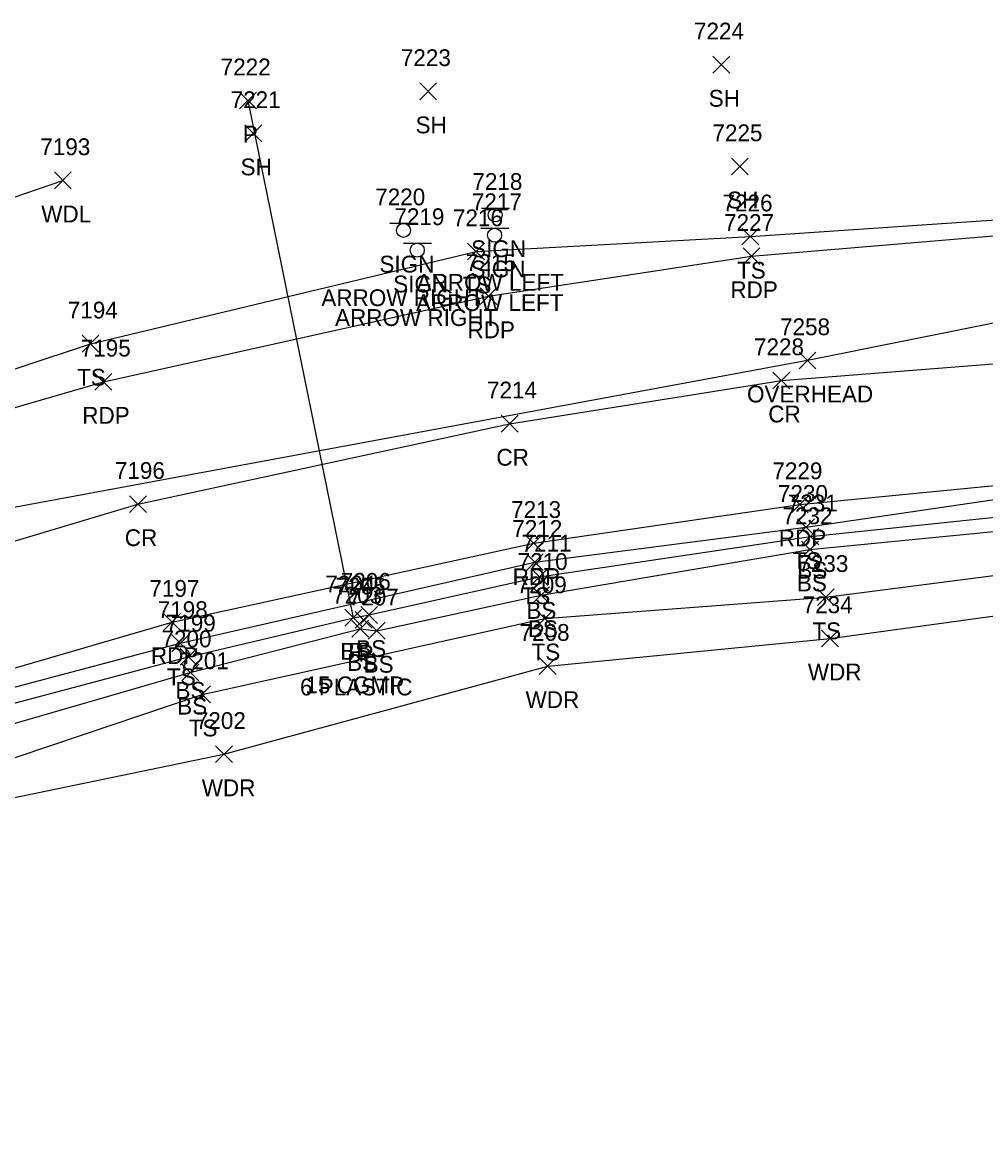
# Model space of a CAD drawing. Extents: x 1611797 to 1633212, y 298978 to 305475.
# Drawn here: x 1624498.3 to 1624612.9, y 304428 to 304561.2 of the extents above; entities that cross this region are included whole.
import ezdxf

# ---------------------------------------------------------------- set-up
doc = ezdxf.new("R2010")
doc.units = 0
for name, color, linetype in [('D_A', 7, 'Continuous'), ('D_C', 7, 'Continuous'), ('D_I', 7, 'Continuous'), ('D_TIC', 7, 'Continuous'), ('DCP', 7, 'Continuous'), ('L_A', 7, 'Continuous'), ('L_C', 7, 'Continuous'), ('L_I', 7, 'Continuous'), ('L_TIC', 7, 'Continuous'), ('LAWA', 7, 'Continuous'), ('LELB', 7, 'Continuous'), ('P_A', 7, 'Continuous'), ('P_I', 7, 'Continuous'), ('P_TIC', 7, 'Continuous'), ('PET', 7, 'Continuous'), ('PRC', 7, 'Continuous'), ('S_A', 7, 'Continuous'), ('S_C', 7, 'Continuous'), ('S_I', 7, 'Continuous'), ('SSGN', 7, 'Continuous'), ('U_A', 7, 'Continuous'), ('U_I', 7, 'Continuous'), ('U_TIC', 7, 'Continuous'), ('UCO', 7, 'Continuous')]:
    doc.layers.add(name, color=color, linetype=linetype)

msp = doc.modelspace()

# ---------------------------------------------------------------- linework, layer by layer
at = {"layer": 'D_TIC'}
for points in [[(1624524.14, 304550.87), (1624526.14, 304552.87)], [(1624526.14, 304550.87), (1624524.14, 304552.87)], [(1624536.67, 304489.32), (1624538.67, 304491.32)], [(1624538.67, 304489.32), (1624536.67, 304491.32)], [(1624537.9, 304489.07), (1624539.9, 304491.07)], [(1624539.9, 304489.07), (1624537.9, 304491.07)]]:
    msp.add_lwpolyline(points, dxfattribs=at)
at = {"layer": 'DCP'}
msp.add_lwpolyline([(1624537.67, 304490.32), (1624525.14, 304551.87)], dxfattribs=at)
at = {"layer": 'L_TIC'}
for points in [[(1624580.46, 304555.14), (1624582.46, 304557.14)], [(1624582.46, 304555.14), (1624580.46, 304557.14)], [(1624545.58, 304551.97), (1624547.58, 304553.97)], [(1624547.58, 304551.97), (1624545.58, 304553.97)], [(1624524.77, 304546.97), (1624526.77, 304548.97)], [(1624526.77, 304546.97), (1624524.77, 304548.97)], [(1624582.66, 304543.03), (1624584.66, 304545.03)], [(1624584.66, 304543.03), (1624582.66, 304545.03)], [(1624502.11, 304541.37), (1624504.11, 304543.37)], [(1624504.11, 304541.37), (1624502.11, 304543.37)], [(1624583.91, 304534.68), (1624585.91, 304536.68)], [(1624585.91, 304534.68), (1624583.91, 304536.68)], [(1624551.27, 304532.91), (1624553.27, 304534.91)], [(1624553.27, 304532.91), (1624551.27, 304534.91)], [(1624505.38, 304521.93), (1624507.38, 304523.93)], [(1624507.38, 304521.93), (1624505.38, 304523.93)], [(1624590.53, 304500.1), (1624592.53, 304502.1)], [(1624592.53, 304500.1), (1624590.53, 304502.1)], [(1624591.05, 304498.97), (1624593.05, 304500.97)], [(1624593.05, 304498.97), (1624591.05, 304500.97)], [(1624591, 304497.44), (1624593, 304499.44)], [(1624593, 304497.44), (1624591, 304499.44)], [(1624558.27, 304495.93), (1624560.27, 304497.93)], [(1624560.27, 304495.93), (1624558.27, 304497.93)], [(1624558.82, 304494.18), (1624560.82, 304496.18)], [(1624560.82, 304494.18), (1624558.82, 304496.18)], [(1624559, 304492), (1624561, 304494)], [(1624561, 304492), (1624559, 304494)], [(1624592.88, 304491.76), (1624594.88, 304493.76)], [(1624594.88, 304491.76), (1624592.88, 304493.76)], [(1624536.67, 304489.32), (1624538.67, 304491.32)], [(1624538.67, 304489.32), (1624536.67, 304491.32)], [(1624538.56, 304489.64), (1624540.56, 304491.64)], [(1624540.56, 304489.64), (1624538.56, 304491.64)], [(1624559.46, 304489.23), (1624561.46, 304491.23)], [(1624561.46, 304489.23), (1624559.46, 304491.23)], [(1624537.49, 304487.99), (1624539.49, 304489.99)], [(1624539.49, 304487.99), (1624537.49, 304489.99)], [(1624539.45, 304487.77), (1624541.45, 304489.77)], [(1624541.45, 304487.77), (1624539.45, 304489.77)], [(1624516.08, 304486.27), (1624518.08, 304488.27)], [(1624518.08, 304486.27), (1624516.08, 304488.27)], [(1624593.39, 304486.85), (1624595.39, 304488.85)], [(1624595.39, 304486.85), (1624593.39, 304488.85)], [(1624517.06, 304484.67), (1624519.06, 304486.67)], [(1624519.06, 304484.67), (1624517.06, 304486.67)], [(1624517.27, 304482.79), (1624519.27, 304484.79)], [(1624519.27, 304482.79), (1624517.27, 304484.79)], [(1624559.79, 304483.56), (1624561.79, 304485.56)], [(1624561.79, 304483.56), (1624559.79, 304485.56)], [(1624518.68, 304480.19), (1624520.68, 304482.19)], [(1624520.68, 304480.19), (1624518.68, 304482.19)], [(1624521.27, 304473.07), (1624523.27, 304475.07)], [(1624523.27, 304473.07), (1624521.27, 304475.07)]]:
    msp.add_lwpolyline(points, dxfattribs=at)
at = {"layer": 'LAWA'}
for points in [[(1624088.25, 304303.5), (1624106.81, 304320.98), (1624153.79, 304356.6), (1624200.5, 304392.1), (1624247.6, 304427), (1624285.25, 304446.91), (1624325.08, 304470.25), (1624369.06, 304488.79), (1624425.3, 304516.01), (1624470.84, 304531.32), (1624503.11, 304542.37)], [(1624186.93, 304294.55), (1624240.75, 304330.36), (1624281.9, 304359.85), (1624320.17, 304387.37), (1624354.03, 304407.62), (1624397.63, 304429.96), (1624419.55, 304440), (1624447.61, 304454.04), (1624487.94, 304466.98), (1624522.27, 304474.07), (1624560.79, 304484.56), (1624594.39, 304487.85), (1624625.21, 304492.09), (1624656.2, 304492.85), (1624695.81, 304490.79), (1624736.39, 304487.29), (1624770.57, 304478.97), (1624808.86, 304473.48), (1624838.37, 304462.56)]]:
    msp.add_lwpolyline(points, dxfattribs=at)
at = {"layer": 'LELB'}
for points in [[(1624095.54, 304298.86), (1624107.13, 304308.7), (1624163.15, 304341.2), (1624211.36, 304376.85), (1624256.11, 304405.01), (1624295.12, 304429.63), (1624332.27, 304455.09), (1624374.78, 304478.34), (1624401.92, 304484.81), (1624434.05, 304498.5), (1624472.98, 304511.84), (1624506.38, 304522.93), (1624552.27, 304533.91), (1624584.91, 304535.68), (1624625.23, 304538.42), (1624653.95, 304544.88), (1624697.41, 304542.2), (1624744.04, 304535.67), (1624782.56, 304529.52), (1624820.4, 304520.29), (1624849.23, 304510.65), (1624882.95, 304501.96), (1624884.04, 304505.26)], [(1624181.13, 304309.78), (1624231.77, 304345.18), (1624273.89, 304372.63), (1624313.92, 304397.95), (1624349.41, 304418.31), (1624391.23, 304441.37), (1624414.63, 304450.88), (1624422.5, 304457.15), (1624425.95, 304456.68), (1624445.07, 304463.44), (1624483.55, 304478.38), (1624517.08, 304487.27), (1624559.27, 304496.93), (1624591.53, 304501.1), (1624624.74, 304505.99)], [(1624181.83, 304308.22), (1624233.12, 304343.37), (1624274.63, 304371.3), (1624314.75, 304397.03), (1624350.32, 304417.49), (1624392.11, 304440.37), (1624415, 304449.13), (1624422.64, 304454.19), (1624424.46, 304454.85), (1624445.65, 304462.42), (1624484.46, 304476.74), (1624518.06, 304485.67), (1624537.67, 304490.32), (1624539.56, 304490.64), (1624559.82, 304495.18), (1624592.05, 304499.97), (1624624.64, 304503.4)], [(1624183.73, 304304.83), (1624234.53, 304340.54), (1624276.44, 304368.9), (1624316.24, 304394.62), (1624351.26, 304415.55), (1624393.38, 304438.07), (1624416.16, 304446.51), (1624422.67, 304451.72), (1624426.18, 304452.72), (1624446.91, 304459), (1624485.37, 304474.27), (1624518.27, 304483.79), (1624538.49, 304488.99), (1624540.45, 304488.77), (1624560, 304493), (1624592, 304498.44), (1624624.83, 304501.63)], [(1624184.93, 304301.87), (1624278.34, 304363.53), (1624318.33, 304391.37), (1624353.31, 304411.71), (1624393.58, 304434.55), (1624417.55, 304442.42), (1624424.34, 304448.67), (1624448.61, 304456.57), (1624487.04, 304470.17), (1624519.68, 304481.19), (1624560.46, 304490.23), (1624593.88, 304492.76), (1624624.32, 304496.68), (1624656.79, 304498.13), (1624695.25, 304497.88), (1624738.57, 304491.31), (1624772.39, 304485.68), (1624810.08, 304476.48), (1624844.46, 304462.44), (1624886.48, 304449.94), (1624926.51, 304437.94), (1624967.18, 304426.7), (1624995.86, 304419.24)]]:
    msp.add_lwpolyline(points, dxfattribs=at)
at = {"layer": 'P_TIC'}
for points in [[(1624584.04, 304532.35), (1624586.04, 304534.35)], [(1624586.04, 304532.35), (1624584.04, 304534.35)], [(1624552.76, 304527.58), (1624554.76, 304529.58)], [(1624554.76, 304527.58), (1624552.76, 304529.58)], [(1624506.92, 304517.4), (1624508.92, 304519.4)], [(1624508.92, 304517.4), (1624506.92, 304519.4)], [(1624587.6, 304517.56), (1624589.6, 304519.56)], [(1624589.6, 304517.56), (1624587.6, 304519.56)], [(1624555.26, 304512.41), (1624557.26, 304514.41)], [(1624557.26, 304512.41), (1624555.26, 304514.41)], [(1624511.04, 304502.84), (1624513.04, 304504.84)], [(1624513.04, 304502.84), (1624511.04, 304504.84)], [(1624589.8, 304502.8), (1624591.8, 304504.8)], [(1624591.8, 304502.8), (1624589.8, 304504.8)], [(1624558.13, 304498.19), (1624560.13, 304500.19)], [(1624560.13, 304498.19), (1624558.13, 304500.19)], [(1624515.09, 304488.8), (1624517.09, 304490.8)], [(1624517.09, 304488.8), (1624515.09, 304490.8)]]:
    msp.add_lwpolyline(points, dxfattribs=at)
at = {"layer": 'PET'}
for points in [[(1624214.6, 304372.95), (1624258.69, 304401.17), (1624298.33, 304425.53), (1624336.86, 304448), (1624379.58, 304470.59), (1624404.49, 304482.1), (1624435.34, 304495.11), (1624473.75, 304508.46), (1624507.92, 304518.4), (1624553.76, 304528.58), (1624585.04, 304533.35), (1624625.18, 304536.71), (1624654.48, 304537.5), (1624696.33, 304535.75), (1624743.35, 304530.33), (1624780.81, 304524.04), (1624819.04, 304514.44), (1624851.35, 304505.26), (1624901.43, 304489.14), (1624942.08, 304475.33), (1624984.5, 304461.2), (1625019.22, 304449.6)], [(1624179.36, 304312.24), (1624229.96, 304347.62), (1624272.13, 304375.05), (1624312.98, 304399.89), (1624348.37, 304420.48), (1624390.3, 304443.15), (1624413.13, 304453.88), (1624422.35, 304458.1), (1624443.89, 304466.53), (1624482.84, 304480.09), (1624516.09, 304489.8), (1624559.13, 304499.19), (1624590.8, 304503.8), (1624624.98, 304507.12)]]:
    msp.add_lwpolyline(points, dxfattribs=at)
at = {"layer": 'PRC'}
msp.add_lwpolyline([(1624172.24, 304325.39), (1624222.29, 304360.15), (1624264.64, 304387.45), (1624305.78, 304412.86), (1624342.45, 304434.67), (1624384.5, 304455.76), (1624409.7, 304467.33), (1624440.42, 304480.07), (1624477.67, 304493.55), (1624512.04, 304503.84), (1624556.26, 304513.41), (1624588.6, 304518.56), (1624625.39, 304521.45), (1624654.72, 304521.97), (1624694.56, 304520.32), (1624741.33, 304515.35), (1624776.51, 304509.39), (1624814.64, 304500.05), (1624847.34, 304490.65), (1624897.27, 304475.63), (1624938.08, 304462.27), (1624974.99, 304449.94), (1625014.51, 304436.37)], dxfattribs=at)
at = {"layer": 'SSGN'}
for p, q in [((1624552.9, 304539.08), (1624556.23, 304539.08)), ((1624554.54, 304538.25), (1624554.54, 304538.25)), ((1624541.99, 304537.26), (1624545.32, 304537.26)), ((1624543.64, 304536.42), (1624543.64, 304536.42)), ((1624552.83, 304536.67), (1624556.17, 304536.67)), ((1624543.62, 304534.9), (1624546.96, 304534.9)), ((1624554.48, 304535.84), (1624554.48, 304535.84)), ((1624545.27, 304534.06), (1624545.27, 304534.06))]:
    msp.add_line(p, q, dxfattribs=at)
for centre in [(1624554.54, 304538.25), (1624543.64, 304536.42), (1624554.48, 304535.84), (1624545.27, 304534.06)]:
    msp.add_circle(centre, 0.833, dxfattribs=at)
at = {"layer": 'U_TIC'}
for points in [[(1624590.7, 304519.94), (1624592.7, 304521.94)], [(1624592.7, 304519.94), (1624590.7, 304521.94)]]:
    msp.add_lwpolyline(points, dxfattribs=at)
at = {"layer": 'UCO'}
msp.add_lwpolyline([(1624859.31, 304474.49), (1624700.84, 304542.82), (1624591.7, 304520.94), (1624421.25, 304489.36)], dxfattribs=at)

# ---------------------------------------------------------------- texts
at = {"layer": 'D_A'}
for p in [(1624524.52, 304546.87), (1624537.04, 304485.32), (1624538.28, 304485.07)]:
    msp.add_text('P', height=2, dxfattribs=at).set_placement(p)
at = {"layer": 'D_C'}
msp.add_text('6 PLASTIC', height=2, dxfattribs=at).set_placement((1624531.32, 304481.07))
at = {"layer": 'D_I'}
for s, p in [('7222', (1624521.88, 304554.87)), ('7204', (1624534.33, 304493.32)), ('7205', (1624535.56, 304493.07))]:
    msp.add_text(s, height=2, dxfattribs=at).set_placement(p)
at = {"layer": 'L_A'}
for s, p in [('SH', (1624579.95, 304551.14)), ('SH', (1624545.07, 304547.97)), ('SH', (1624524.25, 304542.97)), ('SH', (1624582.15, 304539.03)), ('WDL', (1624500.53, 304537.37)), ('TS', (1624583.32, 304530.68)), ('TS', (1624550.68, 304528.91)), ('TS', (1624504.79, 304517.93)), ('TS', (1624589.94, 304496.1)), ('BS', (1624590.49, 304494.97)), ('BS', (1624590.44, 304493.44)), ('TS', (1624557.68, 304491.93)), ('BS', (1624558.26, 304490.18)), ('BS', (1624558.44, 304488)), ('TS', (1624592.29, 304487.76)), ('BS', (1624536.11, 304485.32)), ('BS', (1624538.01, 304485.64)), ('TS', (1624558.87, 304485.23)), ('BS', (1624536.93, 304483.99)), ('BS', (1624538.89, 304483.77)), ('TS', (1624515.49, 304482.27)), ('WDR', (1624591.75, 304482.85)), ('BS', (1624516.5, 304480.67)), ('BS', (1624516.71, 304478.79)), ('WDR', (1624558.16, 304479.56)), ('TS', (1624518.09, 304476.19)), ('WDR', (1624519.63, 304469.07))]:
    msp.add_text(s, height=2, dxfattribs=at).set_placement(p)
at = {"layer": 'L_C'}
msp.add_text('15 CGMP', height=2, dxfattribs=at).set_placement((1624531.96, 304481.32))
at = {"layer": 'L_I'}
for s, p in [('7224', (1624578.2, 304559.14)), ('7223', (1624543.32, 304555.97)), ('7221', (1624523.07, 304550.97)), ('7225', (1624580.4, 304547.03)), ('7193', (1624500.42, 304545.37)), ('7226', (1624581.6, 304538.68)), ('7216', (1624549.52, 304536.91)), ('7194', (1624503.69, 304525.93)), ('7230', (1624588.19, 304504.1)), ('7231', (1624589.35, 304502.97)), ('7232', (1624588.74, 304501.44)), ('7212', (1624556.58, 304499.93)), ('7211', (1624557.69, 304498.18)), ('7210', (1624557.22, 304496)), ('7233', (1624590.62, 304495.76)), ('7204', (1624534.33, 304493.32)), ('7206', (1624536.17, 304493.64)), ('7209', (1624557.11, 304493.23)), ('7203', (1624535.15, 304491.99)), ('7207', (1624537.11, 304491.77)), ('7198', (1624514.39, 304490.27)), ('7234', (1624591.13, 304490.85)), ('7199', (1624515.35, 304488.67)), ('7208', (1624557.45, 304487.56)), ('7200', (1624514.84, 304486.79)), ('7201', (1624516.91, 304484.19)), ('7202', (1624518.93, 304477.07))]:
    msp.add_text(s, height=2, dxfattribs=at).set_placement(p)
at = {"layer": 'P_A'}
for s, p in [('RDP', (1624582.53, 304528.35)), ('RDP', (1624551.25, 304523.58)), ('RDP', (1624505.41, 304513.4)), ('CR', (1624587.04, 304513.56)), ('CR', (1624554.69, 304508.41)), ('CR', (1624510.47, 304498.84)), ('RDP', (1624588.29, 304498.8)), ('RDP', (1624556.62, 304494.19)), ('RDP', (1624513.58, 304484.8))]:
    msp.add_text(s, height=2, dxfattribs=at).set_placement(p)
at = {"layer": 'P_I'}
for s, p in [('7227', (1624581.78, 304536.35)), ('7215', (1624551.07, 304531.58)), ('7195', (1624505.23, 304521.4)), ('7228', (1624585.34, 304521.56)), ('7214', (1624553.57, 304516.41)), ('7196', (1624509.29, 304506.84)), ('7229', (1624587.53, 304506.8)), ('7213', (1624556.44, 304502.19)), ('7197', (1624513.4, 304492.8))]:
    msp.add_text(s, height=2, dxfattribs=at).set_placement(p)
at = {"layer": 'S_A'}
for p in [(1624551.68, 304533.23), (1624540.77, 304531.4), (1624551.62, 304530.82), (1624542.41, 304529.04)]:
    msp.add_text('SIGN', height=2, dxfattribs=at).set_placement(p)
at = {"layer": 'S_C'}
for s, p in [('ARROW LEFT', (1624545.19, 304529.23)), ('ARROW RIGHT', (1624533.86, 304527.4)), ('ARROW LEFT', (1624545.13, 304526.82)), ('ARROW RIGHT', (1624535.49, 304525.04))]:
    msp.add_text(s, height=2, dxfattribs=at).set_placement(p)
at = {"layer": 'S_I'}
for s, p in [('7218', (1624551.83, 304541.23)), ('7220', (1624540.27, 304539.4)), ('7217', (1624551.77, 304538.82)), ('7219', (1624542.55, 304537.04))]:
    msp.add_text(s, height=2, dxfattribs=at).set_placement(p)
at = {"layer": 'U_A'}
msp.add_text('OVERHEAD', height=2, dxfattribs=at).set_placement((1624584.51, 304515.94))
at = {"layer": 'U_I'}
msp.add_text('7258', height=2, dxfattribs=at).set_placement((1624588.44, 304523.94))

doc.saveas('drawing.dxf')
